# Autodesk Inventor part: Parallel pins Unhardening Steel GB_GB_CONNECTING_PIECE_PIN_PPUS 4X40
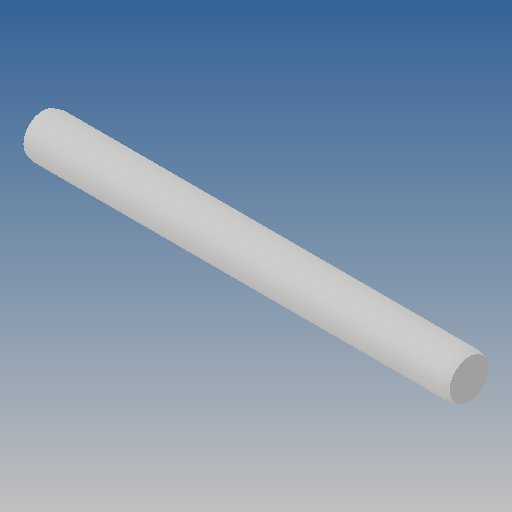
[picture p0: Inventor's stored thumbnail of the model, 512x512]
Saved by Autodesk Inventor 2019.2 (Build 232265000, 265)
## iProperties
Created: 2013-09
Part Number: Parallel pins Unhardening Steel GB_GB_CONNECTING_PIECE_PIN_PPUS 4X40
Material: Ogólny
Document SubType Name: Modeling
Designer: CADENGINEERING4
Density: 1 g/cm^3
Appearance: Domyślna
Author: CADENGINEERING4
Revision Number: ÈÎºÎ
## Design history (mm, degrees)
feature "Base-Revolve"
node "Bryła1"
